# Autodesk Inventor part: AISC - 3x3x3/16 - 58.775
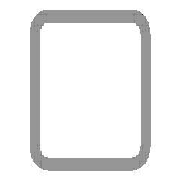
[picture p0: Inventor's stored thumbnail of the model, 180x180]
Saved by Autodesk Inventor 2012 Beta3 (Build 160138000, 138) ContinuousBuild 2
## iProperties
IsCustomPart: 1
Created: 2011-01
Part Number: AISC - 3x3x3/16 - 58.775
Material: Steel, Mild
Description: Tube
Document SubType Name: Modeling
Standard: ANSI
Designer: Beta-8540w
Standards Organization: ANSI
Language: en-US
Size Designation: 3x3x3/16
Categories: <MemberInstance><Categories><Category DisplayName="Structural Shapes" InternalName="089c4875-fa83-4c05-b084-43b9cc11f5ed" Mnemonic="GRDR"><CategoryParameter Dis
Stock Number: 3x3x3/16
Density: 7.86 g/cm^3
_CCFamilyMember: 9
_CCFamilyDisplayName: ANSI AISC (Square) - Tube
_FrameMemberDoc: Frame Member File
_Version: 15.0.0
_GetPNFromCC: 1
G_L: 58.775 in
G_W: 3.000 in
G_H: 3.000 in
+4D71DD38-6577-4695-BB34-97209268B762+CUTDETAIL1: Cut
Author: Beta-8540w
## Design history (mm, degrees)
node "Start plane"
node "End plane"
sketch "Sketch"
  geometry: L1 (-38.1, -28.575)-(-38.1, 28.575); L2 (-28.575, 38.1)-(28.575, 38.1); L3 (38.1, 28.575)-(38.1, -28.575); L4 (28.575, -38.1)-(-28.575, -38.1); L5 (-28.575, 33.337)-(28.575, 33.338); L6 (33.338, 28.575)-(33.338, -28.575); L7 (28.575, -33.337)-(-28.575, -33.338); L8 (-33.338, -28.575)-(-33.338, 28.575); L9 (0, 56.102)-(0, -56.102) reference; L10 (-56.102, 0)-(56.102, 0) reference; A1 r 9.525 centre (-28.575, -28.575) between (-38.1, -28.575) and (-28.575, -38.1); A2 r 9.525 centre (-28.575, 28.575) between (-28.575, 38.1) and (-38.1, 28.575); A3 r 9.525 centre (28.575, 28.575) between (38.1, 28.575) and (28.575, 38.1); A4 r 9.525 centre (28.575, -28.575) between (28.575, -38.1) and (38.1, -28.575); A5 r 4.763 centre (-28.575, 28.575) between (-28.575, 33.337) and (-33.338, 28.575); A6 r 4.763 centre (28.575, 28.575) between (33.338, 28.575) and (28.575, 33.338); A7 r 4.763 centre (28.575, -28.575) between (28.575, -33.337) and (33.338, -28.575); A8 r 4.763 centre (-28.575, -28.575) between (-33.338, -28.575) and (-28.575, -33.338)
  constraints: 16 end point, 16 point on circle, 8 centre point, 8 tangent, 4 parallel, 3 equal radius, 2 perpendicular, 7 other
  dimensions: "d10" = 76.2 distance between parallel lines of L2 L4 (= G_H); "d11" = 76.2 distance between parallel lines of L1 L3 (= G_W); "d12" = 4.7625 distance between parallel lines of L3 L6 (= G_T); "d15" = 38.1 distance between parallel lines of L2 L10 (= 0.5 x d10); "d16" = 38.1 distance between parallel lines of L9 L3 (= 0.5 x d11); "d17" = 9.525 radius of A1 (= G_IR)
extrude "Body" new body sketch "Sketch" stored distance "d3" = 1492.89148 (= G_L); taper "d4" = 0 deg
node "Driven Length"
  sketch "Sketch3"
    geometry: L1 (0, 0)-(10, 0) reference
    constraints: 2 end point, 1 horizontal
  workplane "Work Plane3"
  sketch "Sketch4"
    geometry: L1 (-2, 31.109)-(12, 31.109) reference; L2 (-2, 1524)-(12, 1524) reference
    dimensions: "d19" = 1492.89148 distance between parallel lines of L1 L2 (derived)
workplane "Work Plane4"
split "Split1"
body "Solid1"
other parameters: "G_W" = 76.2 [user parameter; used in 1 equation term], "G_H" = 76.2 [user parameter; used in 1 equation term], "G_T" = 4.7625 [user parameter; used in 1 equation term], "G_IR" = 9.525 [user parameter; used in 1 equation term], "G_L" = 1492.89148 (= d19) [user parameter; used in 1 equation term], "G_OFFSET_START" = -31.10852 [user parameter; used in 1 equation term], "G_OFFSET_END" = 0 [user parameter; used in 1 equation term], "d13" = 31.10852 (= -G_OFFSET_START), "d14" = 1524 (= G_OFFSET_END + B_L), "B_L" = 1524 [user parameter; used in 1 equation term], "d18" = 90 deg
